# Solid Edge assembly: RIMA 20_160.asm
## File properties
Title: Zylinder
Author: ahadarics
Template: iso metric assembly.asm
Last saved by: ahadarics
Revision: 12
Application: Solid Edge
Username: ahadarics
Dokumentum tartalom típus: 1
Document Number: RIMA 20/160
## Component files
Profilrohr.par
Kolbenstange.par
Kit_1.par
Kit_2.par
Mutter_1.par
Mutter_2.par
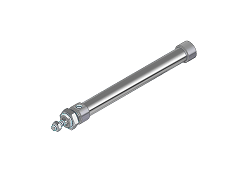
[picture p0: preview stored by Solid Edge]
